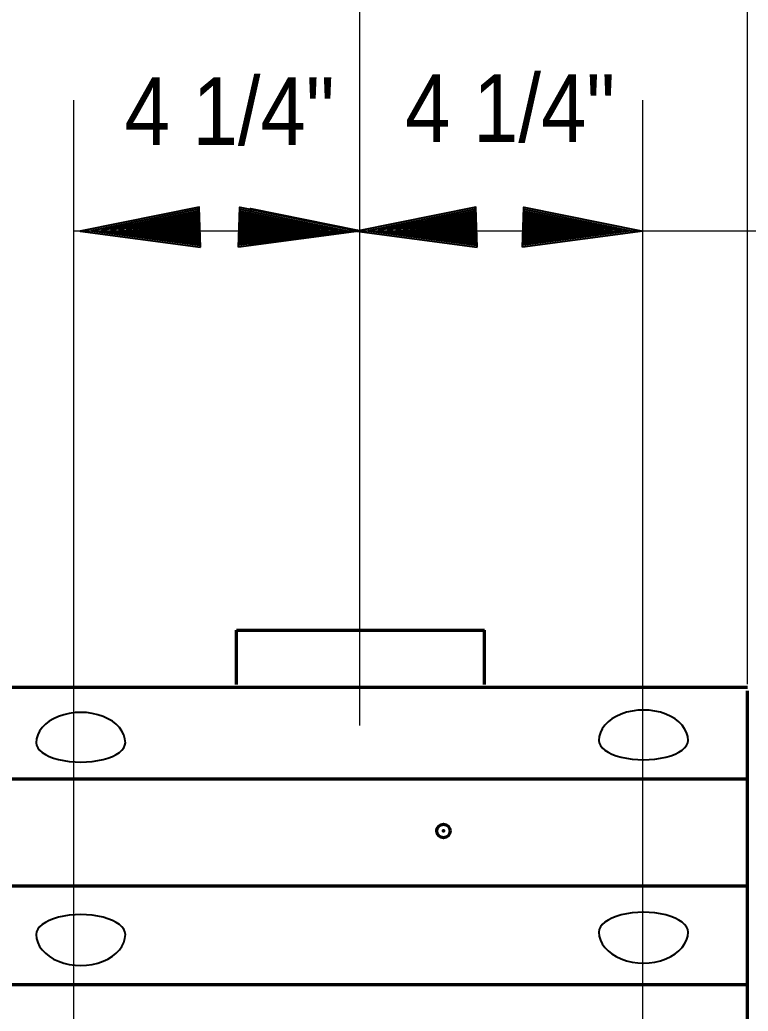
# Model space of a CAD drawing. Extents: x 895.6 to 930.4, y -2278.6 to -2254.7.
# Drawn here: x 921.428 to 922.812, y -2261.437 to -2259.554 of the extents above; entities that cross this region are included whole.
import ezdxf

# ---------------------------------------------------------------- set-up
doc = ezdxf.new("R2010")
doc.units = 0
doc.header["$LTSCALE"] = 0.051
doc.header["$PDMODE"] = 32
doc.header["$PDSIZE"] = 0.0255
for name, color, linetype, lineweight in [('1', 7, 'Continuous', 70), ('3', 7, 'Continuous', 40), ('35', 7, 'Continuous', 70)]:
    doc.layers.add(name, color=color, linetype=linetype, lineweight=lineweight)

msp = doc.modelspace()

# ---------------------------------------------------------------- hatches: boundary and pattern name
at = {"layer": '3'}
for points in [[(921.77083, -2259.98617), (921.76833, -2259.91025), (921.54217, -2259.95592), (921.54217, -2259.95592)], [(921.76967, -2259.98225), (921.76742, -2259.91417), (921.56392, -2259.95517), (921.56392, -2259.95517)], [(921.76867, -2259.97892), (921.76667, -2259.91758), (921.58342, -2259.95458), (921.58342, -2259.95458)], [(921.76767, -2259.97583), (921.76583, -2259.92075), (921.60108, -2259.95392), (921.60108, -2259.95392)], [(921.76692, -2259.97333), (921.76517, -2259.92367), (921.61683, -2259.95342), (921.61683, -2259.95342)], [(921.76592, -2259.97075), (921.76458, -2259.92608), (921.63108, -2259.95308), (921.63108, -2259.95308)], [(921.84308, -2259.98617), (921.84558, -2259.91025), (922.07175, -2259.95592), (922.07175, -2259.95592)], [(921.84425, -2259.98225), (921.84642, -2259.91417), (922.04992, -2259.95517), (922.04992, -2259.95517)], [(921.84525, -2259.97892), (921.84725, -2259.91758), (922.03042, -2259.95458), (922.03042, -2259.95458)], [(921.84625, -2259.97583), (921.84808, -2259.92075), (922.01283, -2259.95392), (922.01283, -2259.95392)], [(921.84692, -2259.97333), (921.84875, -2259.92367), (921.99708, -2259.95342), (921.99708, -2259.95342)], [(921.84792, -2259.97075), (921.84933, -2259.92608), (921.98283, -2259.95308), (921.98283, -2259.95308)], [(921.86375, -2259.98108), (921.86617, -2259.91275), (922.06958, -2259.95383), (922.06958, -2259.95383)], [(922.29667, -2259.98617), (922.29417, -2259.91025), (922.06792, -2259.95592), (922.06792, -2259.95592)], [(922.29542, -2259.98225), (922.29325, -2259.91417), (922.08975, -2259.95517), (922.08975, -2259.95517)], [(922.29442, -2259.97892), (922.29242, -2259.91758), (922.10925, -2259.95458), (922.10925, -2259.95458)], [(922.29342, -2259.97583), (922.29167, -2259.92075), (922.12683, -2259.95392), (922.12683, -2259.95392)], [(922.29275, -2259.97333), (922.29092, -2259.92367), (922.14267, -2259.95342), (922.14267, -2259.95342)], [(922.29175, -2259.97075), (922.29033, -2259.92608), (922.15683, -2259.95308), (922.15683, -2259.95308)], [(922.38267, -2259.98617), (922.38517, -2259.91025), (922.61133, -2259.95592), (922.61133, -2259.95592)], [(922.38383, -2259.98225), (922.38608, -2259.91417), (922.58958, -2259.95517), (922.58958, -2259.95517)], [(922.38483, -2259.97892), (922.38683, -2259.91758), (922.57008, -2259.95458), (922.57008, -2259.95458)], [(922.38583, -2259.97583), (922.38767, -2259.92075), (922.55242, -2259.95392), (922.55242, -2259.95392)], [(922.38658, -2259.97333), (922.38833, -2259.92367), (922.53667, -2259.95342), (922.53667, -2259.95342)], [(922.38758, -2259.97075), (922.38892, -2259.92608), (922.52242, -2259.95308), (922.52242, -2259.95308)], [(921.76542, -2259.96858), (921.76417, -2259.92817), (921.64383, -2259.95242), (921.64383, -2259.95242)], [(921.76475, -2259.96667), (921.76367, -2259.93033), (921.65558, -2259.95225), (921.65558, -2259.95225)], [(921.76433, -2259.96483), (921.76317, -2259.93208), (921.66583, -2259.95167), (921.66583, -2259.95167)], [(921.76375, -2259.96317), (921.76267, -2259.93367), (921.67517, -2259.95158), (921.67517, -2259.95158)], [(921.76325, -2259.96167), (921.76233, -2259.93533), (921.68367, -2259.95117), (921.68367, -2259.95117)], [(921.76292, -2259.96033), (921.76208, -2259.93667), (921.69117, -2259.95075), (921.69117, -2259.95075)], [(921.76242, -2259.95925), (921.76183, -2259.93775), (921.69817, -2259.95067), (921.69817, -2259.95067)], [(921.76208, -2259.95808), (921.76158, -2259.93883), (921.70408, -2259.95058), (921.70408, -2259.95058)], [(921.76183, -2259.95717), (921.76125, -2259.93983), (921.70967, -2259.95033), (921.70967, -2259.95033)], [(921.76158, -2259.95633), (921.76117, -2259.94067), (921.71458, -2259.94992), (921.71458, -2259.94992)], [(921.76133, -2259.95558), (921.76083, -2259.94133), (921.71908, -2259.94983), (921.71908, -2259.94983)], [(921.76117, -2259.95475), (921.76075, -2259.94217), (921.72292, -2259.94975), (921.72292, -2259.94975)], [(921.76083, -2259.95433), (921.76058, -2259.94283), (921.72658, -2259.94975), (921.72658, -2259.94975)], [(921.76067, -2259.95383), (921.76033, -2259.94342), (921.72975, -2259.94975), (921.72975, -2259.94975)], [(921.76042, -2259.95342), (921.76017, -2259.94425), (921.73267, -2259.94983), (921.73267, -2259.94983)], [(921.76042, -2259.95292), (921.76017, -2259.94467), (921.73525, -2259.94975), (921.73525, -2259.94975)], [(921.76025, -2259.95242), (921.75992, -2259.94508), (921.73767, -2259.94942), (921.73767, -2259.94942)], [(921.76017, -2259.95225), (921.75983, -2259.94558), (921.73975, -2259.94958), (921.73975, -2259.94958)], [(921.84842, -2259.96858), (921.84975, -2259.92817), (921.97008, -2259.95242), (921.97008, -2259.95242)], [(921.84917, -2259.96667), (921.85025, -2259.93033), (921.95833, -2259.95225), (921.95833, -2259.95225)], [(921.84958, -2259.96483), (921.85075, -2259.93208), (921.94808, -2259.95167), (921.94808, -2259.95167)], [(921.85017, -2259.96317), (921.85125, -2259.93367), (921.93875, -2259.95158), (921.93875, -2259.95158)], [(921.85067, -2259.96167), (921.85158, -2259.93533), (921.93025, -2259.95117), (921.93025, -2259.95117)], [(921.85092, -2259.96033), (921.85183, -2259.93667), (921.92275, -2259.95075), (921.92275, -2259.95075)], [(921.85142, -2259.95925), (921.85208, -2259.93775), (921.91575, -2259.95067), (921.91575, -2259.95067)], [(921.85183, -2259.95808), (921.85233, -2259.93883), (921.90983, -2259.95058), (921.90983, -2259.95058)], [(921.85208, -2259.95717), (921.85267, -2259.93983), (921.90425, -2259.95033), (921.90425, -2259.95033)], [(921.85233, -2259.95633), (921.85275, -2259.94067), (921.89933, -2259.94992), (921.89933, -2259.94992)], [(921.85258, -2259.95558), (921.85308, -2259.94133), (921.89483, -2259.94983), (921.89483, -2259.94983)], [(921.85275, -2259.95475), (921.85317, -2259.94217), (921.89092, -2259.94975), (921.89092, -2259.94975)], [(921.85308, -2259.95433), (921.85333, -2259.94283), (921.88733, -2259.94975), (921.88733, -2259.94975)], [(921.85325, -2259.95383), (921.85358, -2259.94342), (921.88417, -2259.94975), (921.88417, -2259.94975)], [(921.85342, -2259.95342), (921.85375, -2259.94425), (921.88125, -2259.94983), (921.88125, -2259.94983)], [(921.85342, -2259.95292), (921.85375, -2259.94467), (921.87867, -2259.94975), (921.87867, -2259.94975)], [(921.85367, -2259.95242), (921.85392, -2259.94508), (921.87625, -2259.94942), (921.87625, -2259.94942)], [(921.85375, -2259.95225), (921.85408, -2259.94558), (921.87417, -2259.94958), (921.87417, -2259.94958)], [(922.29125, -2259.96858), (922.28992, -2259.92817), (922.16967, -2259.95242), (922.16967, -2259.95242)], [(922.29058, -2259.96667), (922.28942, -2259.93033), (922.18133, -2259.95225), (922.18133, -2259.95225)], [(922.29017, -2259.96483), (922.28892, -2259.93208), (922.19167, -2259.95167), (922.19167, -2259.95167)], [(922.28958, -2259.96317), (922.28842, -2259.93367), (922.20092, -2259.95158), (922.20092, -2259.95158)], [(922.28908, -2259.96167), (922.28817, -2259.93533), (922.20942, -2259.95117), (922.20942, -2259.95117)], [(922.28875, -2259.96033), (922.28783, -2259.93667), (922.21692, -2259.95075), (922.21692, -2259.95075)], [(922.28825, -2259.95925), (922.28767, -2259.93775), (922.22392, -2259.95067), (922.22392, -2259.95067)], [(922.28783, -2259.95808), (922.28733, -2259.93883), (922.22983, -2259.95058), (922.22983, -2259.95058)], [(922.28767, -2259.95717), (922.28708, -2259.93983), (922.23542, -2259.95033), (922.23542, -2259.95033)], [(922.28733, -2259.95633), (922.28692, -2259.94067), (922.24033, -2259.94992), (922.24033, -2259.94992)], [(922.28717, -2259.95558), (922.28667, -2259.94133), (922.24483, -2259.94983), (922.24483, -2259.94983)], [(922.28692, -2259.95475), (922.28658, -2259.94217), (922.24875, -2259.94975), (922.24875, -2259.94975)], [(922.28667, -2259.95433), (922.28633, -2259.94283), (922.25233, -2259.94975), (922.25233, -2259.94975)], [(922.28642, -2259.95383), (922.28617, -2259.94342), (922.25558, -2259.94975), (922.25558, -2259.94975)], [(922.28625, -2259.95342), (922.28592, -2259.94425), (922.25842, -2259.94983), (922.25842, -2259.94983)], [(922.28625, -2259.95292), (922.28592, -2259.94467), (922.26108, -2259.94975), (922.26108, -2259.94975)], [(922.28608, -2259.95242), (922.28575, -2259.94508), (922.26342, -2259.94942), (922.26342, -2259.94942)], [(922.28592, -2259.95225), (922.28567, -2259.94558), (922.26558, -2259.94958), (922.26558, -2259.94958)], [(922.38808, -2259.96858), (922.38933, -2259.92817), (922.50967, -2259.95242), (922.50967, -2259.95242)], [(922.38875, -2259.96667), (922.38983, -2259.93033), (922.49792, -2259.95225), (922.49792, -2259.95225)], [(922.38917, -2259.96483), (922.39033, -2259.93208), (922.48767, -2259.95167), (922.48767, -2259.95167)], [(922.38975, -2259.96317), (922.39083, -2259.93367), (922.47833, -2259.95158), (922.47833, -2259.95158)], [(922.39025, -2259.96167), (922.39117, -2259.93533), (922.46983, -2259.95117), (922.46983, -2259.95117)], [(922.39058, -2259.96033), (922.39142, -2259.93667), (922.46233, -2259.95075), (922.46233, -2259.95075)], [(922.39108, -2259.95925), (922.39167, -2259.93775), (922.45533, -2259.95067), (922.45533, -2259.95067)], [(922.39142, -2259.95808), (922.39192, -2259.93883), (922.44942, -2259.95058), (922.44942, -2259.95058)], [(922.39167, -2259.95717), (922.39225, -2259.93983), (922.44383, -2259.95033), (922.44383, -2259.95033)], [(922.39192, -2259.95633), (922.39233, -2259.94067), (922.43892, -2259.94992), (922.43892, -2259.94992)], [(922.39217, -2259.95558), (922.39267, -2259.94133), (922.43442, -2259.94983), (922.43442, -2259.94983)], [(922.39233, -2259.95475), (922.39275, -2259.94217), (922.43058, -2259.94975), (922.43058, -2259.94975)], [(922.39267, -2259.95433), (922.39292, -2259.94283), (922.42692, -2259.94975), (922.42692, -2259.94975)], [(922.39283, -2259.95383), (922.39317, -2259.94342), (922.42375, -2259.94975), (922.42375, -2259.94975)], [(922.39308, -2259.95342), (922.39333, -2259.94425), (922.42083, -2259.94983), (922.42083, -2259.94983)], [(922.39308, -2259.95292), (922.39333, -2259.94467), (922.41825, -2259.94975), (922.41825, -2259.94975)], [(922.39325, -2259.95242), (922.39358, -2259.94508), (922.41583, -2259.94942), (922.41583, -2259.94942)], [(922.39333, -2259.95225), (922.39367, -2259.94558), (922.41375, -2259.94958), (922.41375, -2259.94958)]]:
    msp.add_hatch(color=256, dxfattribs=at).paths.add_polyline_path(points)

# ---------------------------------------------------------------- linework, layer by layer
at = {"layer": '1', "lineweight": 25}
for p, q in [((922.81042, -2260.81608), (922.81042, -2258.57183)), ((922.07367, -2260.89433), (922.07367, -2258.95492)), ((921.53067, -2262.60458), (921.53067, -2259.70667)), ((922.61158, -2262.44942), (922.61158, -2259.70667)), ((923.22417, -2259.95542), (921.53067, -2259.95542))]:
    msp.add_line(p, q, dxfattribs=at)
at = {"layer": '1'}
for p, q in [((921.30733, -2260.82175), (922.81058, -2260.82175)), ((922.81058, -2262.27175), (922.81058, -2260.82867)), ((921.30733, -2260.99608), (922.81058, -2260.99608)), ((921.30733, -2261.19933), (922.81058, -2261.19933)), ((921.30733, -2261.38625), (922.81058, -2261.38625))]:
    msp.add_line(p, q, dxfattribs=at)
at = {"layer": '1', "lineweight": 40}
for centre, major_axis, ratio in [((922.61267, -2260.92279), (0.08469, 0), 0.679978), ((921.54359, -2260.92729), (0.08469, 0), 0.679978), ((922.61267, -2260.92279), (-0.08469, 0), 0.434256), ((921.54359, -2260.92729), (-0.08469, 0), 0.434256), ((921.54359, -2261.29137), (0.08469, 0), 0.442883), ((922.61267, -2261.28687), (0.08469, 0), 0.442883), ((921.54359, -2261.29137), (-0.08469, 0), 0.696674), ((922.61267, -2261.28687), (-0.08469, 0), 0.696674)]:
    msp.add_ellipse(centre, major_axis=major_axis, ratio=ratio, start_param=6.2831853, end_param=9.424778, dxfattribs=at)
at = {"layer": '1'}
msp.add_point((922.23258, -2261.09492), dxfattribs=at)
at = {"layer": '3'}
for points in [[(921.77083, -2259.98617), (921.76833, -2259.91025), (921.54217, -2259.95592), (921.54217, -2259.95592)], [(921.76967, -2259.98225), (921.76742, -2259.91417), (921.56392, -2259.95517), (921.56392, -2259.95517)], [(921.76867, -2259.97892), (921.76667, -2259.91758), (921.58342, -2259.95458), (921.58342, -2259.95458)], [(921.76767, -2259.97583), (921.76583, -2259.92075), (921.60108, -2259.95392), (921.60108, -2259.95392)], [(921.76692, -2259.97333), (921.76517, -2259.92367), (921.61683, -2259.95342), (921.61683, -2259.95342)], [(921.76592, -2259.97075), (921.76458, -2259.92608), (921.63108, -2259.95308), (921.63108, -2259.95308)], [(921.84308, -2259.98617), (921.84558, -2259.91025), (922.07175, -2259.95592), (922.07175, -2259.95592)], [(921.84425, -2259.98225), (921.84642, -2259.91417), (922.04992, -2259.95517), (922.04992, -2259.95517)], [(921.84525, -2259.97892), (921.84725, -2259.91758), (922.03042, -2259.95458), (922.03042, -2259.95458)], [(921.84625, -2259.97583), (921.84808, -2259.92075), (922.01283, -2259.95392), (922.01283, -2259.95392)], [(921.84692, -2259.97333), (921.84875, -2259.92367), (921.99708, -2259.95342), (921.99708, -2259.95342)], [(921.84792, -2259.97075), (921.84933, -2259.92608), (921.98283, -2259.95308), (921.98283, -2259.95308)], [(921.86375, -2259.98108), (921.86617, -2259.91275), (922.06958, -2259.95383), (922.06958, -2259.95383)], [(922.29667, -2259.98617), (922.29417, -2259.91025), (922.06792, -2259.95592), (922.06792, -2259.95592)], [(922.29542, -2259.98225), (922.29325, -2259.91417), (922.08975, -2259.95517), (922.08975, -2259.95517)], [(922.29442, -2259.97892), (922.29242, -2259.91758), (922.10925, -2259.95458), (922.10925, -2259.95458)], [(922.29342, -2259.97583), (922.29167, -2259.92075), (922.12683, -2259.95392), (922.12683, -2259.95392)], [(922.29275, -2259.97333), (922.29092, -2259.92367), (922.14267, -2259.95342), (922.14267, -2259.95342)], [(922.29175, -2259.97075), (922.29033, -2259.92608), (922.15683, -2259.95308), (922.15683, -2259.95308)], [(922.38267, -2259.98617), (922.38517, -2259.91025), (922.61133, -2259.95592), (922.61133, -2259.95592)], [(922.38383, -2259.98225), (922.38608, -2259.91417), (922.58958, -2259.95517), (922.58958, -2259.95517)], [(922.38483, -2259.97892), (922.38683, -2259.91758), (922.57008, -2259.95458), (922.57008, -2259.95458)], [(922.38583, -2259.97583), (922.38767, -2259.92075), (922.55242, -2259.95392), (922.55242, -2259.95392)], [(922.38658, -2259.97333), (922.38833, -2259.92367), (922.53667, -2259.95342), (922.53667, -2259.95342)], [(922.38758, -2259.97075), (922.38892, -2259.92608), (922.52242, -2259.95308), (922.52242, -2259.95308)], [(921.76542, -2259.96858), (921.76417, -2259.92817), (921.64383, -2259.95242), (921.64383, -2259.95242)], [(921.76475, -2259.96667), (921.76367, -2259.93033), (921.65558, -2259.95225), (921.65558, -2259.95225)], [(921.76433, -2259.96483), (921.76317, -2259.93208), (921.66583, -2259.95167), (921.66583, -2259.95167)], [(921.76375, -2259.96317), (921.76267, -2259.93367), (921.67517, -2259.95158), (921.67517, -2259.95158)], [(921.76325, -2259.96167), (921.76233, -2259.93533), (921.68367, -2259.95117), (921.68367, -2259.95117)], [(921.76292, -2259.96033), (921.76208, -2259.93667), (921.69117, -2259.95075), (921.69117, -2259.95075)], [(921.76242, -2259.95925), (921.76183, -2259.93775), (921.69817, -2259.95067), (921.69817, -2259.95067)], [(921.76208, -2259.95808), (921.76158, -2259.93883), (921.70408, -2259.95058), (921.70408, -2259.95058)], [(921.76183, -2259.95717), (921.76125, -2259.93983), (921.70967, -2259.95033), (921.70967, -2259.95033)], [(921.76158, -2259.95633), (921.76117, -2259.94067), (921.71458, -2259.94992), (921.71458, -2259.94992)], [(921.76133, -2259.95558), (921.76083, -2259.94133), (921.71908, -2259.94983), (921.71908, -2259.94983)], [(921.76117, -2259.95475), (921.76075, -2259.94217), (921.72292, -2259.94975), (921.72292, -2259.94975)], [(921.76083, -2259.95433), (921.76058, -2259.94283), (921.72658, -2259.94975), (921.72658, -2259.94975)], [(921.76067, -2259.95383), (921.76033, -2259.94342), (921.72975, -2259.94975), (921.72975, -2259.94975)], [(921.76042, -2259.95342), (921.76017, -2259.94425), (921.73267, -2259.94983), (921.73267, -2259.94983)], [(921.76042, -2259.95292), (921.76017, -2259.94467), (921.73525, -2259.94975), (921.73525, -2259.94975)], [(921.76025, -2259.95242), (921.75992, -2259.94508), (921.73767, -2259.94942), (921.73767, -2259.94942)], [(921.76017, -2259.95225), (921.75983, -2259.94558), (921.73975, -2259.94958), (921.73975, -2259.94958)], [(921.84842, -2259.96858), (921.84975, -2259.92817), (921.97008, -2259.95242), (921.97008, -2259.95242)], [(921.84917, -2259.96667), (921.85025, -2259.93033), (921.95833, -2259.95225), (921.95833, -2259.95225)], [(921.84958, -2259.96483), (921.85075, -2259.93208), (921.94808, -2259.95167), (921.94808, -2259.95167)], [(921.85017, -2259.96317), (921.85125, -2259.93367), (921.93875, -2259.95158), (921.93875, -2259.95158)], [(921.85067, -2259.96167), (921.85158, -2259.93533), (921.93025, -2259.95117), (921.93025, -2259.95117)], [(921.85092, -2259.96033), (921.85183, -2259.93667), (921.92275, -2259.95075), (921.92275, -2259.95075)], [(921.85142, -2259.95925), (921.85208, -2259.93775), (921.91575, -2259.95067), (921.91575, -2259.95067)], [(921.85183, -2259.95808), (921.85233, -2259.93883), (921.90983, -2259.95058), (921.90983, -2259.95058)], [(921.85208, -2259.95717), (921.85267, -2259.93983), (921.90425, -2259.95033), (921.90425, -2259.95033)], [(921.85233, -2259.95633), (921.85275, -2259.94067), (921.89933, -2259.94992), (921.89933, -2259.94992)], [(921.85258, -2259.95558), (921.85308, -2259.94133), (921.89483, -2259.94983), (921.89483, -2259.94983)], [(921.85275, -2259.95475), (921.85317, -2259.94217), (921.89092, -2259.94975), (921.89092, -2259.94975)], [(921.85308, -2259.95433), (921.85333, -2259.94283), (921.88733, -2259.94975), (921.88733, -2259.94975)], [(921.85325, -2259.95383), (921.85358, -2259.94342), (921.88417, -2259.94975), (921.88417, -2259.94975)], [(921.85342, -2259.95342), (921.85375, -2259.94425), (921.88125, -2259.94983), (921.88125, -2259.94983)], [(921.85342, -2259.95292), (921.85375, -2259.94467), (921.87867, -2259.94975), (921.87867, -2259.94975)], [(921.85367, -2259.95242), (921.85392, -2259.94508), (921.87625, -2259.94942), (921.87625, -2259.94942)], [(921.85375, -2259.95225), (921.85408, -2259.94558), (921.87417, -2259.94958), (921.87417, -2259.94958)], [(922.29125, -2259.96858), (922.28992, -2259.92817), (922.16967, -2259.95242), (922.16967, -2259.95242)], [(922.29058, -2259.96667), (922.28942, -2259.93033), (922.18133, -2259.95225), (922.18133, -2259.95225)], [(922.29017, -2259.96483), (922.28892, -2259.93208), (922.19167, -2259.95167), (922.19167, -2259.95167)], [(922.28958, -2259.96317), (922.28842, -2259.93367), (922.20092, -2259.95158), (922.20092, -2259.95158)], [(922.28908, -2259.96167), (922.28817, -2259.93533), (922.20942, -2259.95117), (922.20942, -2259.95117)], [(922.28875, -2259.96033), (922.28783, -2259.93667), (922.21692, -2259.95075), (922.21692, -2259.95075)], [(922.28825, -2259.95925), (922.28767, -2259.93775), (922.22392, -2259.95067), (922.22392, -2259.95067)], [(922.28783, -2259.95808), (922.28733, -2259.93883), (922.22983, -2259.95058), (922.22983, -2259.95058)], [(922.28767, -2259.95717), (922.28708, -2259.93983), (922.23542, -2259.95033), (922.23542, -2259.95033)], [(922.28733, -2259.95633), (922.28692, -2259.94067), (922.24033, -2259.94992), (922.24033, -2259.94992)], [(922.28717, -2259.95558), (922.28667, -2259.94133), (922.24483, -2259.94983), (922.24483, -2259.94983)], [(922.28692, -2259.95475), (922.28658, -2259.94217), (922.24875, -2259.94975), (922.24875, -2259.94975)], [(922.28667, -2259.95433), (922.28633, -2259.94283), (922.25233, -2259.94975), (922.25233, -2259.94975)], [(922.28642, -2259.95383), (922.28617, -2259.94342), (922.25558, -2259.94975), (922.25558, -2259.94975)], [(922.28625, -2259.95342), (922.28592, -2259.94425), (922.25842, -2259.94983), (922.25842, -2259.94983)], [(922.28625, -2259.95292), (922.28592, -2259.94467), (922.26108, -2259.94975), (922.26108, -2259.94975)], [(922.28608, -2259.95242), (922.28575, -2259.94508), (922.26342, -2259.94942), (922.26342, -2259.94942)], [(922.28592, -2259.95225), (922.28567, -2259.94558), (922.26558, -2259.94958), (922.26558, -2259.94958)], [(922.38808, -2259.96858), (922.38933, -2259.92817), (922.50967, -2259.95242), (922.50967, -2259.95242)], [(922.38875, -2259.96667), (922.38983, -2259.93033), (922.49792, -2259.95225), (922.49792, -2259.95225)], [(922.38917, -2259.96483), (922.39033, -2259.93208), (922.48767, -2259.95167), (922.48767, -2259.95167)], [(922.38975, -2259.96317), (922.39083, -2259.93367), (922.47833, -2259.95158), (922.47833, -2259.95158)], [(922.39025, -2259.96167), (922.39117, -2259.93533), (922.46983, -2259.95117), (922.46983, -2259.95117)], [(922.39058, -2259.96033), (922.39142, -2259.93667), (922.46233, -2259.95075), (922.46233, -2259.95075)], [(922.39108, -2259.95925), (922.39167, -2259.93775), (922.45533, -2259.95067), (922.45533, -2259.95067)], [(922.39142, -2259.95808), (922.39192, -2259.93883), (922.44942, -2259.95058), (922.44942, -2259.95058)], [(922.39167, -2259.95717), (922.39225, -2259.93983), (922.44383, -2259.95033), (922.44383, -2259.95033)], [(922.39192, -2259.95633), (922.39233, -2259.94067), (922.43892, -2259.94992), (922.43892, -2259.94992)], [(922.39217, -2259.95558), (922.39267, -2259.94133), (922.43442, -2259.94983), (922.43442, -2259.94983)], [(922.39233, -2259.95475), (922.39275, -2259.94217), (922.43058, -2259.94975), (922.43058, -2259.94975)], [(922.39267, -2259.95433), (922.39292, -2259.94283), (922.42692, -2259.94975), (922.42692, -2259.94975)], [(922.39283, -2259.95383), (922.39317, -2259.94342), (922.42375, -2259.94975), (922.42375, -2259.94975)], [(922.39308, -2259.95342), (922.39333, -2259.94425), (922.42083, -2259.94983), (922.42083, -2259.94983)], [(922.39308, -2259.95292), (922.39333, -2259.94467), (922.41825, -2259.94975), (922.41825, -2259.94975)], [(922.39325, -2259.95242), (922.39358, -2259.94508), (922.41583, -2259.94942), (922.41583, -2259.94942)], [(922.39333, -2259.95225), (922.39367, -2259.94558), (922.41375, -2259.94958), (922.41375, -2259.94958)]]:
    msp.add_lwpolyline(points, close=True, dxfattribs=at)
at = {"layer": '35'}
for p, q in [((921.83917, -2260.71333), (922.31042, -2260.71333)), ((921.83917, -2260.81658), (921.83917, -2260.71333)), ((922.31042, -2260.81658), (922.31042, -2260.71333))]:
    msp.add_line(p, q, dxfattribs=at)

# ---------------------------------------------------------------- texts
at = {"layer": '1', "width": 0.9}
for p in [(921.62683, -2259.79225), (922.15975, -2259.78642)]:
    msp.add_text('4 1/4"', height=0.1286, dxfattribs=at).set_placement(p)

doc.saveas('drawing.dxf')
